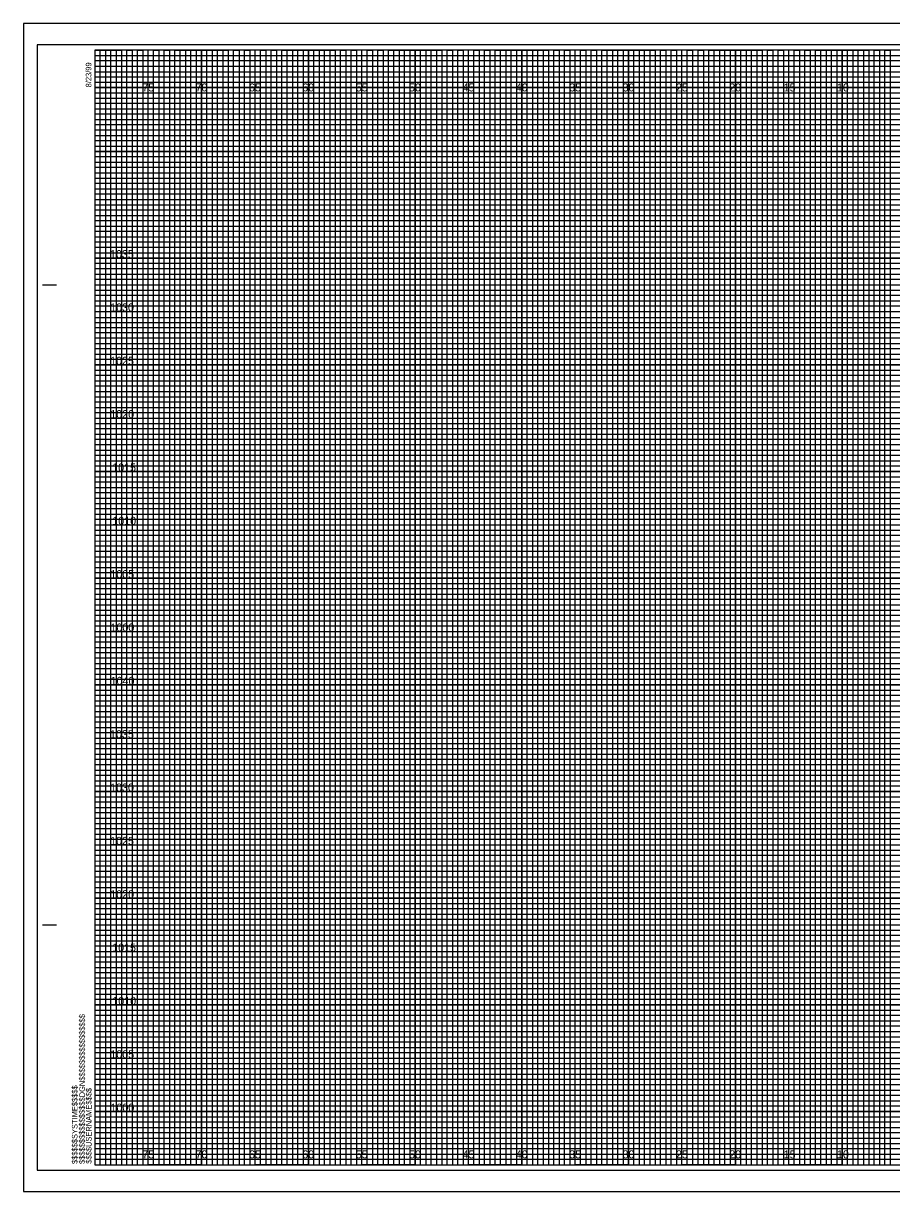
# Model space of a CAD drawing. Extents: x -7 to 162, y -2 to 987.
# Drawn here: x -6.7 to 74.6, y 327.5 to 437 of the extents above; entities that cross this region are included whole.
import ezdxf

# ---------------------------------------------------------------- set-up
doc = ezdxf.new("R2010")
doc.units = 0
for name, color, linetype in [('Exist Cross Section Cell', 7, 'Continuous'), ('Exist XS Center Line Elevation Label', 7, 'Continuous'), ('Exist XS Ground Line', 7, 'Continuous'), ('Prop CMT Concrete Structures', 7, 'Continuous'), ('Prop CMT Guardrail Widen Shoulder', 7, 'Continuous'), ('Prop CMT Pvmt Course 1', 7, 'Continuous'), ('Prop CMT Pvmt Surface', 7, 'Continuous'), ('Prop CMT Shld Paved Course 1', 7, 'Continuous'), ('Prop CMT Slope Grass', 7, 'Continuous'), ('Prop CMT Subgrade Earthwork', 7, 'Continuous'), ('Typical Text Label CELL', 7, 'Continuous')]:
    doc.layers.add(name, color=color, linetype=linetype)

msp = doc.modelspace()

# ---------------------------------------------------------------- linework, layer by layer
at = {"layer": 'Exist XS Center Line Elevation Label'}
for points in [[(0, 434.5), (2.5, 434.5), (2.5, 330), (7.5, 330), (7.5, 434.5), (12.5, 434.5), (12.5, 330), (17.5, 330), (17.5, 434.5), (22.5, 434.5), (22.5, 330), (27.5, 330), (27.5, 434.5), (32.5, 434.5), (32.5, 330), (37.5, 330), (37.5, 434.5), (42.5, 434.5), (42.5, 330), (47.5, 330), (47.5, 434.5), (52.5, 434.5), (52.5, 330), (57.5, 330), (57.5, 434.5), (62.5, 434.5), (62.5, 330), (67.5, 330), (67.5, 434.5), (72.5, 434.5), (72.5, 330), (77.5, 330)], [(0, 432), (137.5, 432)], [(0, 422.5), (160, 422.5), (160, 427.5), (0, 427.5)], [(0, 412.5), (160, 412.5), (160, 417.5), (0, 417.5)], [(0, 402.5), (160, 402.5), (160, 407.5), (0, 407.5)], [(0, 392.5), (160, 392.5), (160, 397.5), (0, 397.5)], [(0, 382.5), (160, 382.5), (160, 387.5), (0, 387.5)], [(0, 372.5), (160, 372.5), (160, 377.5), (0, 377.5)], [(0, 362.5), (160, 362.5), (160, 367.5), (0, 367.5)], [(0, 352.5), (160, 352.5), (160, 357.5), (0, 357.5)], [(0, 342.5), (160, 342.5), (160, 347.5), (0, 347.5)], [(0, 332.5), (160, 332.5), (160, 337.5), (0, 337.5)]]:
    msp.add_lwpolyline(points, dxfattribs=at)
at = {"layer": 'Exist XS Ground Line'}
for p, q in [((5, 434.5), (0, 434.5)), ((5, 330), (5, 434.5)), ((15, 434.5), (10, 434.5)), ((10, 434.5), (10, 330)), ((15, 330), (15, 434.5)), ((25, 434.5), (20, 434.5)), ((20, 434.5), (20, 330)), ((25, 330), (25, 434.5)), ((35, 434.5), (30, 434.5)), ((30, 434.5), (30, 330)), ((35, 330), (35, 434.5)), ((45, 434.5), (40, 434.5)), ((40, 434.5), (40, 330)), ((45, 330), (45, 434.5)), ((55, 434.5), (50, 434.5)), ((50, 434.5), (50, 330)), ((55, 330), (55, 434.5)), ((65, 434.5), (60, 434.5)), ((60, 434.5), (60, 330)), ((65, 330), (65, 434.5)), ((75, 434.5), (70, 434.5)), ((70, 434.5), (70, 330)), ((10, 330), (5, 330)), ((20, 330), (15, 330)), ((30, 330), (25, 330)), ((40, 330), (35, 330)), ((50, 330), (45, 330)), ((60, 330), (55, 330)), ((70, 330), (65, 330))]:
    msp.add_line(p, q, dxfattribs=at)
for points in [[(0, 430), (160, 430), (160, 425), (0, 425)], [(0, 420), (160, 420), (160, 415), (0, 415)], [(0, 410), (160, 410), (160, 405), (0, 405)], [(0, 400), (160, 400), (160, 395), (0, 395)], [(0, 390), (160, 390), (160, 385), (0, 385)], [(0, 380), (160, 380), (160, 375), (0, 375)], [(0, 370), (160, 370), (160, 365), (0, 365)], [(0, 360), (160, 360), (160, 355), (0, 355)], [(0, 350), (160, 350), (160, 345), (0, 345)], [(0, 340), (160, 340), (160, 335), (0, 335)]]:
    msp.add_lwpolyline(points, dxfattribs=at)
at = {"layer": 'Prop CMT Concrete Structures'}
for p, q in [((5, 330), (5, 434.5)), ((10, 330), (10, 434.5)), ((15, 330), (15, 434.5)), ((20, 330), (20, 434.5)), ((25, 330), (25, 434.5)), ((30, 330), (30, 434.5)), ((35, 330), (35, 434.5)), ((40, 330), (40, 434.5)), ((45, 330), (45, 434.5)), ((50, 330), (50, 434.5)), ((55, 330), (55, 434.5)), ((60, 330), (60, 434.5)), ((65, 330), (65, 434.5)), ((70, 330), (70, 434.5)), ((0, 430), (160, 430)), ((0, 425), (160, 425)), ((0, 420), (160, 420)), ((0, 415), (160, 415)), ((0, 410), (160, 410)), ((0, 405), (160, 405)), ((0, 400), (160, 400)), ((0, 395), (160, 395)), ((0, 390), (160, 390)), ((0, 385), (160, 385)), ((0, 380), (160, 380)), ((0, 375), (160, 375)), ((0, 370), (160, 370)), ((0, 365), (160, 365)), ((0, 360), (160, 360)), ((0, 355), (160, 355)), ((0, 350), (160, 350)), ((0, 345), (160, 345)), ((0, 340), (160, 340)), ((0, 335), (160, 335))]:
    msp.add_line(p, q, dxfattribs=at)
at = {"layer": 'Prop CMT Guardrail Widen Shoulder'}
for p, q in [((161.65, 437), (-6.7, 437)), ((-6.7, 437), (-6.7, 327.5)), ((-6.7, 327.5), (161.65, 327.5))]:
    msp.add_line(p, q, dxfattribs=at)
at = {"layer": 'Prop CMT Pvmt Course 1'}
msp.add_lwpolyline([(-6.7, 327.5), (161.65, 327.5), (161.65, 437), (-6.7, 437)], close=True, dxfattribs=at)
at = {"layer": 'Prop CMT Pvmt Surface'}
for points in [[(0, 330), (0.5, 330), (0.5, 434.5), (1, 434.5), (1, 330)], [(1, 330), (1.5, 330), (1.5, 434.5), (2, 434.5), (2, 330)], [(2.5, 330), (3, 330), (3, 434.5), (3.5, 434.5), (3.5, 330)], [(3.5, 330), (4, 330), (4, 434.5), (4.5, 434.5), (4.5, 330)], [(5, 330), (5.5, 330), (5.5, 434.5), (6, 434.5), (6, 330)], [(6, 330), (6.5, 330), (6.5, 434.5), (7, 434.5), (7, 330)], [(7.5, 330), (8, 330), (8, 434.5), (8.5, 434.5), (8.5, 330)], [(8.5, 330), (9, 330), (9, 434.5), (9.5, 434.5), (9.5, 330)], [(10, 330), (10.5, 330), (10.5, 434.5), (11, 434.5), (11, 330)], [(11, 330), (11.5, 330), (11.5, 434.5), (12, 434.5), (12, 330)], [(12.5, 330), (13, 330), (13, 434.5), (13.5, 434.5), (13.5, 330)], [(13.5, 330), (14, 330), (14, 434.5), (14.5, 434.5), (14.5, 330)], [(15, 330), (15.5, 330), (15.5, 434.5), (16, 434.5), (16, 330)], [(16, 330), (16.5, 330), (16.5, 434.5), (17, 434.5), (17, 330)], [(17.5, 330), (18, 330), (18, 434.5), (18.5, 434.5), (18.5, 330)], [(18.5, 330), (19, 330), (19, 434.5), (19.5, 434.5), (19.5, 330)], [(20, 330), (20.5, 330), (20.5, 434.5), (21, 434.5), (21, 330)], [(21, 330), (21.5, 330), (21.5, 434.5), (22, 434.5), (22, 330)], [(22.5, 330), (23, 330), (23, 434.5), (23.5, 434.5), (23.5, 330)], [(23.5, 330), (24, 330), (24, 434.5), (24.5, 434.5), (24.5, 330)], [(25, 330), (25.5, 330), (25.5, 434.5), (26, 434.5), (26, 330)], [(26, 330), (26.5, 330), (26.5, 434.5), (27, 434.5), (27, 330)], [(27.5, 330), (28, 330), (28, 434.5), (28.5, 434.5), (28.5, 330)], [(28.5, 330), (29, 330), (29, 434.5), (29.5, 434.5), (29.5, 330)], [(30, 330), (30.5, 330), (30.5, 434.5), (31, 434.5), (31, 330)], [(31, 330), (31.5, 330), (31.5, 434.5), (32, 434.5), (32, 330)], [(32.5, 330), (33, 330), (33, 434.5), (33.5, 434.5), (33.5, 330)], [(33.5, 330), (34, 330), (34, 434.5), (34.5, 434.5), (34.5, 330)], [(35, 330), (35.5, 330), (35.5, 434.5), (36, 434.5), (36, 330)], [(36, 330), (36.5, 330), (36.5, 434.5), (37, 434.5), (37, 330)], [(37.5, 330), (38, 330), (38, 434.5), (38.5, 434.5), (38.5, 330)], [(38.5, 330), (39, 330), (39, 434.5), (39.5, 434.5), (39.5, 330)], [(40, 330), (40.5, 330), (40.5, 434.5), (41, 434.5), (41, 330)], [(41, 330), (41.5, 330), (41.5, 434.5), (42, 434.5), (42, 330)], [(42.5, 330), (43, 330), (43, 434.5), (43.5, 434.5), (43.5, 330)], [(43.5, 330), (44, 330), (44, 434.5), (44.5, 434.5), (44.5, 330)], [(45, 330), (45.5, 330), (45.5, 434.5), (46, 434.5), (46, 330)], [(46, 330), (46.5, 330), (46.5, 434.5), (47, 434.5), (47, 330)], [(47.5, 330), (48, 330), (48, 434.5), (48.5, 434.5), (48.5, 330)], [(48.5, 330), (49, 330), (49, 434.5), (49.5, 434.5), (49.5, 330)], [(50, 330), (50.5, 330), (50.5, 434.5), (51, 434.5), (51, 330)], [(51, 330), (51.5, 330), (51.5, 434.5), (52, 434.5), (52, 330)], [(52.5, 330), (53, 330), (53, 434.5), (53.5, 434.5), (53.5, 330)], [(53.5, 330), (54, 330), (54, 434.5), (54.5, 434.5), (54.5, 330)], [(55, 330), (55.5, 330), (55.5, 434.5), (56, 434.5), (56, 330)], [(56, 330), (56.5, 330), (56.5, 434.5), (57, 434.5), (57, 330)], [(57.5, 330), (58, 330), (58, 434.5), (58.5, 434.5), (58.5, 330)], [(58.5, 330), (59, 330), (59, 434.5), (59.5, 434.5), (59.5, 330)], [(60, 330), (60.5, 330), (60.5, 434.5), (61, 434.5), (61, 330)], [(61, 330), (61.5, 330), (61.5, 434.5), (62, 434.5), (62, 330)], [(62.5, 330), (63, 330), (63, 434.5), (63.5, 434.5), (63.5, 330)], [(63.5, 330), (64, 330), (64, 434.5), (64.5, 434.5), (64.5, 330)], [(65, 330), (65.5, 330), (65.5, 434.5), (66, 434.5), (66, 330)], [(66, 330), (66.5, 330), (66.5, 434.5), (67, 434.5), (67, 330)], [(67.5, 330), (68, 330), (68, 434.5), (68.5, 434.5), (68.5, 330)], [(68.5, 330), (69, 330), (69, 434.5), (69.5, 434.5), (69.5, 330)], [(70, 330), (70.5, 330), (70.5, 434.5), (71, 434.5), (71, 330)], [(71, 330), (71.5, 330), (71.5, 434.5), (72, 434.5), (72, 330)], [(72.5, 330), (73, 330), (73, 434.5), (73.5, 434.5), (73.5, 330)], [(73.5, 330), (74, 330), (74, 434.5), (74.5, 434.5), (74.5, 330)]]:
    msp.add_lwpolyline(points, dxfattribs=at)
at = {"layer": 'Prop CMT Shld Paved Course 1'}
for p, q in [((0, 434), (130, 434)), ((130, 433.49), (0, 433.49)), ((0, 433.49), (0, 433)), ((0, 433), (130, 433)), ((130, 432.44), (0, 432.44)), ((0, 432.44), (0, 431.5)), ((0, 431.5), (160, 431.5))]:
    msp.add_line(p, q, dxfattribs=at)
for points in [[(0, 431), (135, 431), (160, 431), (160, 431), (0, 431)], [(0, 430.5), (160, 430.5), (160, 429.5), (0, 429.5)], [(0, 429), (160, 429), (160, 428.5), (0, 428.49)], [(0, 428), (160, 428), (160, 427), (0, 427)], [(0, 426.5), (160, 426.5), (160, 426), (0, 426)], [(0, 425.5), (160, 425.5), (160, 424.5), (0, 424.5)], [(0, 424), (160, 424), (160, 423.5), (0, 423.5)], [(0, 423), (160, 423), (160, 422), (0, 422)], [(0, 421.5), (160, 421.5), (160, 421), (0, 421)], [(0, 420.5), (160, 420.5), (160, 419.5), (0, 419.5)], [(0, 419), (160, 419), (160, 418.5), (0, 418.5)], [(0, 418), (160, 418), (160, 416.98), (160, 416.5), (160, 416), (0, 416)], [(0, 417), (160, 417), (160, 416.5), (0, 416.5)], [(0, 415.5), (160, 415.5), (160, 414.5), (0, 414.51)], [(0, 414.51), (160, 414.5), (160, 414), (0, 414)], [(0, 413.5), (160, 413.5), (160, 413), (0, 413)], [(0, 412), (160, 412), (160, 411.5), (0, 411.5)], [(0, 411), (160, 411), (160, 410.5), (0, 410.5)], [(-0.04, 409.44), (160, 409.44), (160, 408.94), (-0.04, 408.94)], [(0, 408.5), (160, 408.5), (160, 408), (0, 408)], [(0, 407), (160, 407), (160, 406.5), (0, 406.5)], [(0, 406), (160, 406), (160, 405.5), (0, 405.5)], [(0, 404.5), (160, 404.5), (160, 404), (0, 404)], [(0, 403.5), (160, 403.5), (160, 403), (0, 403)], [(0, 402), (160, 402), (160, 401.5), (0, 401.5)], [(0, 401), (160, 401), (160, 400.5), (0, 400.5)], [(0, 399.5), (160, 399.5), (160, 398.99), (0, 399)], [(0, 398.5), (160, 398.5), (160, 398), (0, 398)], [(0, 397), (160, 397), (160, 396.5), (0, 396.5)], [(0, 396), (160, 396), (160, 395.5), (0, 395.5)], [(0, 394.5), (160, 394.5), (160, 394), (0, 394)], [(0, 393.5), (160, 393.5), (160, 393), (0, 393)], [(0, 392), (160, 392), (160, 391.5), (0, 391.5)], [(0, 391), (160, 391), (160, 390.5), (0, 390.5)], [(0, 389.5), (160, 389.5), (160, 389), (0, 389)], [(0, 388.5), (160.03, 388.45), (160, 388), (0, 388)], [(0, 387), (160, 387), (160, 386.5), (0, 386.5)], [(0, 386), (160, 386), (160, 385.5), (0, 385.5)], [(0, 384.5), (160, 384.5), (160, 384), (0, 384)], [(0, 383.5), (160, 383.5), (160, 383), (0, 383)], [(0, 382), (160, 382), (160, 381.5), (0, 381.5)], [(0, 381), (160, 381), (160, 380.5), (0, 380.5)], [(0, 379.5), (160, 379.5), (160, 379), (0, 379)], [(0, 378.5), (160, 378.5), (160, 378), (0, 378)], [(0, 377), (160, 377), (160, 376.5), (0, 376.5)], [(0, 376), (160, 376), (160, 375.5), (0, 375.5)], [(0, 374.5), (160, 374.5), (160, 374), (0, 374)], [(0, 373.5), (160, 373.5), (160, 373), (0, 373)], [(0, 372), (160, 372), (160, 371.5), (0, 371.5)], [(0, 371), (160, 371), (160, 370.5), (0, 370.5)], [(0, 369.5), (160, 369.5), (160, 368.99), (0, 369)], [(0, 368.5), (160, 368.5), (160, 368), (0, 368)], [(0, 367), (160, 367), (160, 366.5), (0, 366.5)], [(0, 366), (160, 366), (160, 365.5), (0, 365.5)], [(0, 364.5), (160, 364.5), (160, 364), (0, 364)], [(0, 363.5), (160, 363.5), (160, 363), (0, 363)], [(0, 362), (160, 362), (160, 361.5), (0, 361.5)], [(0, 361), (160, 361), (160, 360.5), (0, 360.5)], [(0, 359.5), (160, 359.5), (160, 359), (0, 359)], [(0, 358.5), (160.03, 358.45), (160, 358), (0, 358)], [(0, 357), (160, 357), (160, 356.5), (0, 356.5)], [(0, 356), (160, 356), (160, 355.5), (0, 355.5)], [(0, 354.5), (160, 354.5), (160, 354), (0, 354)], [(0, 353.5), (160, 353.5), (160, 353), (0, 353)], [(0, 352), (160, 352), (160, 351.5), (0, 351.5)], [(0, 351), (160, 351), (160, 350.5), (0, 350.5)], [(0, 349.5), (160, 349.5), (160, 349), (0, 349)], [(0, 348.5), (160, 348.5), (160, 348), (0, 348)], [(0, 347), (160, 347), (160, 346.5), (0, 346.5)], [(0, 346), (160, 346), (160, 345.5), (0, 345.5)], [(0, 344.5), (160, 344.5), (160, 344), (0, 344)], [(0, 343.5), (160, 343.5), (160, 343), (0, 343)], [(0, 342), (160, 342), (160, 341.5), (0, 341.5)], [(0, 341), (160, 341), (160, 340.5), (0, 340.5)], [(0, 339.5), (160, 339.5), (160, 339), (0, 339)], [(0, 338.5), (160, 338.5), (160, 338), (0, 338)], [(0, 337), (160, 337), (160, 336.5), (0, 336.5)], [(0, 336), (160, 336), (160, 335.5), (0, 335.5)], [(0, 334.5), (160, 334.5), (160, 334), (0, 334)], [(0, 333.5), (160, 333.5), (160, 333), (0, 333)], [(0, 332), (160, 332), (160, 331.5), (0, 331.5)], [(0, 331), (160, 331), (160, 330.5), (0, 330.5)]]:
    msp.add_lwpolyline(points, dxfattribs=at)
at = {"layer": 'Prop CMT Slope Grass'}
msp.add_lwpolyline([(-5.4, 329.5), (161.2, 329.5), (161.2, 435), (-5.4, 435)], close=True, dxfattribs=at)
at = {"layer": 'Prop CMT Subgrade Earthwork'}
for p, q in [((-4.9, 412.5), (-3.65, 412.5)), ((-4.85, 412.5), (-3.6, 412.5)), ((-4.9, 352.5), (-3.65, 352.5)), ((-4.85, 352.5), (-3.6, 352.5)), ((0, 330), (0, 330)), ((0, 330), (0, 330)), ((0, 330), (0, 330)), ((0, 330), (0, 330)), ((0, 330), (0, 330)), ((0, 330), (0, 330)), ((0, 330), (0, 330))]:
    msp.add_line(p, q, dxfattribs=at)
msp.add_lwpolyline([(160, 434.5), (0, 434.5), (0, 330), (160, 330)], close=True, dxfattribs=at)

# ---------------------------------------------------------------- texts
at = {"layer": 'Exist Cross Section Cell'}
for s, p in [('75', (4.44, 430.62)), ('70', (9.43, 430.62)), ('65', (14.44, 430.62)), ('60', (19.43, 430.62)), ('55', (24.44, 430.62)), ('50', (29.43, 430.62)), ('45', (34.44, 430.62)), ('40', (39.43, 430.62)), ('35', (44.44, 430.62)), ('30', (49.43, 430.62)), ('25', (54.44, 430.62)), ('20', (59.43, 430.62)), ('15', (64.53, 430.62)), ('10', (69.52, 430.62)), ('75', (4.44, 330.62)), ('70', (9.43, 330.62)), ('65', (14.44, 330.62)), ('60', (19.43, 330.62)), ('55', (24.44, 330.62)), ('50', (29.43, 330.62)), ('45', (34.44, 330.62)), ('40', (39.43, 330.62)), ('35', (44.44, 330.62)), ('30', (49.43, 330.62)), ('25', (54.44, 330.62)), ('20', (59.43, 330.62)), ('15', (64.53, 330.62)), ('10', (69.52, 330.62))]:
    msp.add_text(s, height=0.75, dxfattribs=at).set_placement(p)
at = {"layer": 'Prop CMT Subgrade Earthwork'}
for s, p in [('8/23/99', (-0.33, 431)), ('$$$$$$$$$$$$$$$$DGN$$$$$$$$$$$$$$$$', (-0.94, 330.09)), ('$$$$$$SYSTIME$$$$$', (-1.63, 330.09)), ('$$$$USERNAME$$$$', (-0.31, 330.12))]:
    msp.add_text(s, height=0.525, rotation=90, dxfattribs=at).set_placement(p)
at = {"layer": 'Typical Text Label CELL'}
for s, p in [('1035', (1.42, 415)), ('1030', (1.43, 410)), ('1025', (1.43, 405)), ('1020', (1.44, 400)), ('1015', (1.62, 395)), ('1010', (1.63, 390)), ('1005', (1.45, 385)), ('1000', (1.46, 380)), ('1040', (1.47, 375)), ('1035', (1.42, 370)), ('1030', (1.43, 365)), ('1025', (1.43, 360)), ('1020', (1.44, 355)), ('1015', (1.62, 350)), ('1010', (1.63, 345)), ('1005', (1.45, 340)), ('1000', (1.46, 335))]:
    msp.add_text(s, height=0.75, dxfattribs=at).set_placement(p)

doc.saveas('drawing.dxf')
